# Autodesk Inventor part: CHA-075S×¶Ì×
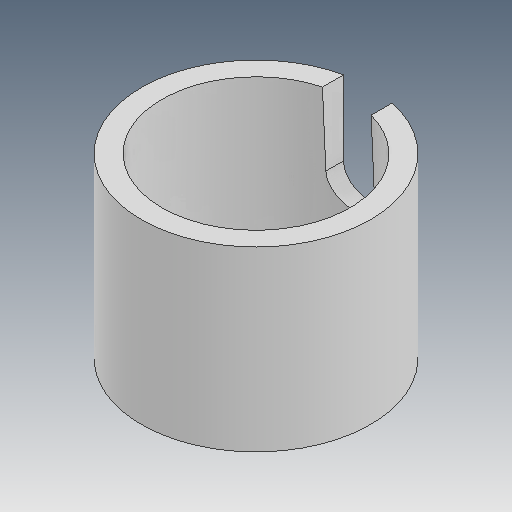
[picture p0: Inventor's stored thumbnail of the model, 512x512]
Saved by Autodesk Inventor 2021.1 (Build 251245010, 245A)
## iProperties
Created: 2019-12
Part Number: CHA-075S×¶Ì×
Material: Ogólny
Document SubType Name: Modeling
Designer: user
Density: 1 g/cm^3
Appearance: Domyślna
Author: user
Revision Number: ÈÎºÎ
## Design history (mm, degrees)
feature "ÊäÈë1"
node "Bryła1"
